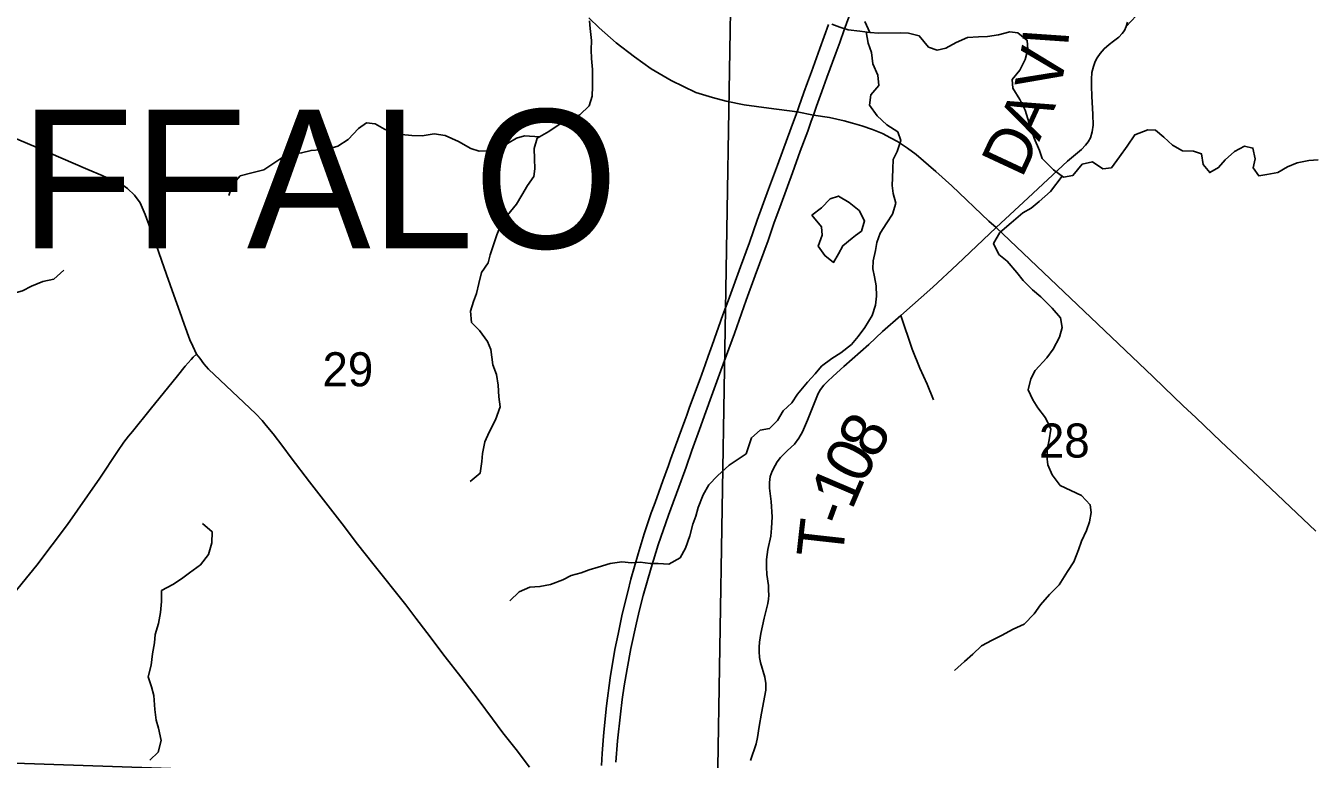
# Model space of a CAD drawing. Extents: x 0 to 34, y 0 to 22.
# Drawn here: x 6.508 to 8.087, y 16.577 to 17.478 of the extents above; entities that cross this region are included whole.
import ezdxf

# ---------------------------------------------------------------- set-up
doc = ezdxf.new("R2010")
doc.units = 0
for name, color, linetype in [('GM_X_Corporation', 7, 'Continuous'), ('GM_X_County_Road', 7, 'Continuous'), ('GM_X_County_Road_Text', 7, 'Continuous'), ('GM_X_Interstate_Route', 7, 'Continuous'), ('GM_X_Minor_Lake', 7, 'Continuous'), ('GM_X_Minor_River', 7, 'Continuous'), ('GM_X_Section_Text', 7, 'Continuous'), ('GM_X_State_Route', 7, 'Continuous'), ('GM_X_Township_Road', 7, 'Continuous'), ('GM_X_Township_Road_Text', 7, 'Continuous'), ('GM_X_Township_Text', 7, 'Continuous')]:
    doc.layers.add(name, color=color, linetype=linetype)

msp = doc.modelspace()

# ---------------------------------------------------------------- linework, layer by layer
at = {"layer": 'GM_X_Corporation'}
for points in [[(6.3854, 17.5878), (7.375, 17.5696), (7.3577, 16.5425), (6.3626, 16.5761)], [(7.375, 17.5696), (8.4063, 17.5538), (8.3875, 16.5502), (7.3577, 16.5425)]]:
    msp.add_lwpolyline(points, close=True, dxfattribs=at)
at = {"layer": 'GM_X_County_Road'}
for points in [[(7.8612, 17.4819), (7.8596, 17.4768)], [(7.8596, 17.4768), (7.8576, 17.4718), (7.8547, 17.468), (7.8507, 17.4635), (7.8441, 17.4588), (7.8386, 17.4544), (7.8325, 17.4493), (7.8276, 17.4437), (7.824, 17.4384), (7.8217, 17.4336), (7.8197, 17.4274), (7.8176, 17.4201), (7.8171, 17.4121), (7.8172, 17.4035), (7.8177, 17.3911), (7.8189, 17.3684), (7.819, 17.3553), (7.8178, 17.3472), (7.8159, 17.3401), (7.8132, 17.335), (7.8098, 17.3309), (7.8049, 17.3256), (7.7878, 17.3114), (7.7394, 17.2663), (7.6999, 17.2299)], [(7.1269, 16.5667), (7.1104, 16.5886), (7.094, 16.6091), (7.0812, 16.6263), (7.0639, 16.6502), (7.0426, 16.6779), (7.0231, 16.7026), (7.0009, 16.7322), (6.9871, 16.75), (6.9748, 16.7661), (6.9343, 16.8171), (6.9154, 16.841), (6.8968, 16.8657), (6.8565, 16.9175), (6.8342, 16.9467), (6.8238, 16.9606), (6.8118, 16.9763), (6.8035, 16.9865), (6.7983, 16.9928), (6.7908, 17.001), (6.7468, 17.0423), (6.7327, 17.0558), (6.7269, 17.0625), (6.7217, 17.0691), (6.7179, 17.0741), (6.7131, 17.084), (6.7098, 17.092), (6.7027, 17.1109), (6.6972, 17.1264), (6.6901, 17.1465), (6.6811, 17.1719), (6.6652, 17.2167), (6.6547, 17.2458), (6.6485, 17.2599), (6.6418, 17.2696), (6.633, 17.2777), (6.6272, 17.2817), (6.6189, 17.286), (6.602, 17.2938), (6.5842, 17.3012), (6.521, 17.3283), (6.4674, 17.3509)]]:
    msp.add_lwpolyline(points, dxfattribs=at)
at = {"layer": 'GM_X_Interstate_Route'}
for points in [[(7.4729, 17.3604), (7.4756, 17.3679), (7.4792, 17.3787), (7.486, 17.3967), (7.4922, 17.4142), (7.5031, 17.4439), (7.5079, 17.4571), (7.5134, 17.4725), (7.5247, 17.5037)], [(7.2154, 16.5688), (7.2161, 16.5835), (7.2176, 16.6048), (7.2185, 16.614), (7.2214, 16.6422), (7.2259, 16.6767), (7.2318, 16.7114), (7.2356, 16.7304), (7.2407, 16.7548), (7.2474, 16.7823), (7.2513, 16.7978), (7.2603, 16.829), (7.2678, 16.8537), (7.2764, 16.8792), (7.2799, 16.8886), (7.2831, 16.8978), (7.2906, 16.9187), (7.2974, 16.9373), (7.2999, 16.9449), (7.3105, 16.9737), (7.3176, 16.9927), (7.32, 16.9993), (7.3233, 17.009), (7.3363, 17.044), (7.3424, 17.0611), (7.3463, 17.0718), (7.3512, 17.0854), (7.3644, 17.1226), (7.3707, 17.1397), (7.3858, 17.1814), (7.3969, 17.2112), (7.4065, 17.2389), (7.4204, 17.277), (7.4313, 17.3063), (7.4438, 17.3401), (7.451, 17.3601), (7.4554, 17.3718), (7.4577, 17.3782), (7.4639, 17.3958), (7.4682, 17.4079), (7.4731, 17.4209), (7.4834, 17.4496), (7.4942, 17.4793)], [(7.2328, 16.573), (7.2348, 16.5992), (7.2384, 16.632), (7.2406, 16.6499), (7.243, 16.6667), (7.2468, 16.6875), (7.2513, 16.7125), (7.2583, 16.7442), (7.2619, 16.76), (7.2665, 16.7776), (7.2762, 16.8119), (7.285, 16.8399), (7.2975, 16.8763), (7.3129, 16.9187), (7.3192, 16.9354), (7.3263, 16.9557), (7.3374, 16.986), (7.3418, 16.9988), (7.352, 17.0272), (7.3619, 17.0542), (7.3786, 17.0996), (7.393, 17.1407), (7.4042, 17.1709), (7.4198, 17.214), (7.4271, 17.2345), (7.4359, 17.2587), (7.4497, 17.2968), (7.4594, 17.3237), (7.4686, 17.3482), (7.4729, 17.3604)]]:
    msp.add_lwpolyline(points, dxfattribs=at)
at = {"layer": 'GM_X_Minor_Lake'}
for points in [[(7.5274, 17.2198), (7.5347, 17.2253), (7.5384, 17.2378), (7.5316, 17.2507), (7.5194, 17.2605), (7.5062, 17.2684), (7.496, 17.265), (7.4854, 17.2539), (7.4737, 17.2448)], [(7.4737, 17.2448), (7.4855, 17.2308), (7.4862, 17.2202), (7.4814, 17.2069), (7.4894, 17.1952), (7.5004, 17.1869), (7.5064, 17.1975), (7.5117, 17.2074), (7.523, 17.2165), (7.5274, 17.2198)]]:
    msp.add_lwpolyline(points, dxfattribs=at)
at = {"layer": 'GM_X_Minor_River'}
for points in [[(7.2004, 17.4838), (7.2015, 17.4743), (7.2031, 17.4596), (7.2024, 17.4482), (7.2028, 17.4372), (7.2043, 17.4239), (7.2044, 17.4126), (7.204, 17.4031), (7.2037, 17.3913), (7.2003, 17.3792), (7.1886, 17.3682), (7.1776, 17.3628), (7.1659, 17.3578), (7.1504, 17.3479), (7.1364, 17.3395), (7.1327, 17.327), (7.1331, 17.3141), (7.1335, 17.302), (7.132, 17.2925), (7.1245, 17.2815), (7.1173, 17.2697), (7.1109, 17.2583), (7.0996, 17.245), (7.0917, 17.2329), (7.0868, 17.2207), (7.0834, 17.2109), (7.0785, 17.1961), (7.0759, 17.1862), (7.068, 17.1744), (7.0646, 17.1611), (7.0616, 17.1486), (7.0579, 17.1387), (7.0545, 17.127), (7.0557, 17.1133), (7.0656, 17.1031), (7.0751, 17.0899), (7.0793, 17.0801), (7.0816, 17.0611), (7.0862, 17.0494), (7.0885, 17.0361), (7.0893, 17.0217), (7.0908, 17.0096), (7.0852, 16.9937), (7.0773, 16.9785), (7.072, 16.9667), (7.069, 16.9523), (7.0683, 16.9424), (7.0661, 16.928), (7.054, 16.9177)], [(7.5385, 17.4827), (7.545, 17.4695)], [(7.5404, 17.47), (7.5427, 17.4562), (7.5469, 17.4448), (7.5485, 17.4308), (7.5546, 17.4168), (7.5558, 17.4043), (7.5459, 17.3929), (7.5445, 17.38), (7.554, 17.3671), (7.5657, 17.3558), (7.5794, 17.3471), (7.5828, 17.3365), (7.5783, 17.3233), (7.5734, 17.3134), (7.5731, 17.302), (7.5727, 17.291), (7.5724, 17.2812), (7.5736, 17.2717), (7.5766, 17.2596), (7.5725, 17.2463), (7.5657, 17.2356), (7.5574, 17.2227), (7.5533, 17.2113), (7.5518, 17.2015), (7.5488, 17.189), (7.5485, 17.1791), (7.5504, 17.1693), (7.5527, 17.1583), (7.5531, 17.1454), (7.552, 17.1344), (7.5475, 17.1215), (7.5385, 17.1071), (7.5305, 17.0957), (7.5222, 17.0861), (7.5094, 17.0759), (7.4981, 17.069), (7.4856, 17.0595), (7.4777, 17.05), (7.4682, 17.0397), (7.4558, 17.0249), (7.449, 17.0143), (7.4384, 17.0044), (7.4316, 16.9926), (7.4218, 16.9827), (7.4101, 16.9808), (7.3995, 16.9713), (7.3961, 16.9618), (7.3931, 16.9519), (7.3818, 16.9443), (7.372, 16.9378), (7.3576, 16.9249), (7.3471, 16.9138), (7.3403, 16.9013), (7.3339, 16.8857), (7.3313, 16.8751), (7.3275, 16.8652), (7.3238, 16.8512), (7.3185, 16.836), (7.3117, 16.8239), (7.2981, 16.8162), (7.2849, 16.817), (7.275, 16.8169), (7.2629, 16.8188), (7.2523, 16.818), (7.2402, 16.8191), (7.2258, 16.8171), (7.2111, 16.8125), (7.2001, 16.8091), (7.1902, 16.8056), (7.1781, 16.8022), (7.1676, 16.7968), (7.1528, 16.7911), (7.1396, 16.7888), (7.1274, 16.788), (7.1142, 16.7822), (7.1025, 16.7712)], [(7.498, 17.4795), (7.5078, 17.4758), (7.5184, 17.4728), (7.5325, 17.4709), (7.545, 17.4695)], [(7.545, 17.4695), (7.5559, 17.4687), (7.5821, 17.4688), (7.5923, 17.4685), (7.6056, 17.4651), (7.617, 17.4515), (7.6276, 17.4478), (7.6382, 17.4501), (7.651, 17.4569), (7.665, 17.463), (7.6783, 17.4642), (7.6892, 17.4643), (7.7029, 17.4666), (7.7169, 17.47), (7.7267, 17.4689), (7.7381, 17.4595), (7.7389, 17.4485), (7.7355, 17.436), (7.7291, 17.4231)], [(7.7291, 17.4231), (7.7197, 17.4117), (7.7205, 17.4011), (7.7292, 17.3871), (7.7357, 17.3738), (7.7388, 17.3632), (7.7426, 17.3515), (7.7468, 17.3394), (7.7533, 17.3242), (7.7567, 17.3144), (7.7704, 17.3008), (7.7829, 17.2917), (7.7942, 17.2937), (7.8056, 17.3074), (7.8184, 17.3104), (7.8309, 17.3018), (7.8415, 17.3029), (7.8517, 17.3166), (7.8608, 17.3299), (7.8702, 17.3436), (7.8861, 17.3497), (7.8959, 17.3494), (7.9058, 17.3407), (7.9164, 17.3309), (7.9289, 17.3241), (7.9422, 17.3237), (7.9521, 17.3204), (7.9544, 17.3071), (7.9623, 17.2973), (7.9733, 17.3034), (7.9812, 17.3129), (7.9926, 17.3232), (8.005, 17.3296), (8.0153, 17.3274), (8.0183, 17.3141), (8.0157, 17.3031), (8.0226, 17.2933), (8.0324, 17.2949), (8.046, 17.2972), (8.0577, 17.3044), (8.0698, 17.3094), (8.0842, 17.3121), (8.0956, 17.3129)], [(7.1394, 17.3413), (7.1205, 17.3425), (7.1107, 17.3395), (7.0997, 17.333), (7.0884, 17.328), (7.0755, 17.3238), (7.0649, 17.3234), (7.0547, 17.3267), (7.0395, 17.3354), (7.0232, 17.3429), (7.0096, 17.3448), (6.9948, 17.3425), (6.9823, 17.3428), (6.9694, 17.3439), (6.9596, 17.3461), (6.9486, 17.3506), (6.9372, 17.357), (6.9266, 17.3585), (6.9168, 17.3513), (6.9039, 17.338), (6.8915, 17.3296), (6.8816, 17.3269), (6.8695, 17.3253), (6.8586, 17.3245), (6.8468, 17.3215), (6.8336, 17.3203), (6.8226, 17.3153), (6.8128, 17.3088), (6.8007, 17.3008), (6.7859, 17.297), (6.7716, 17.2932), (6.7617, 17.2817), (6.7576, 17.2692)], [(7.7812, 17.293), (7.7667, 17.2739), (7.7527, 17.2617), (7.7429, 17.2537), (7.7327, 17.248), (7.7183, 17.2354), (7.7047, 17.2236), (7.6968, 17.2103), (7.7033, 17.1967), (7.7135, 17.1884), (7.7253, 17.1744), (7.7333, 17.1646), (7.7447, 17.1532), (7.7549, 17.1446), (7.7686, 17.1306), (7.7789, 17.1189), (7.7812, 17.1068), (7.7778, 17.095), (7.7699, 17.0802), (7.7623, 17.0695), (7.748, 17.0543), (7.7427, 17.0441), (7.7394, 17.0304), (7.7451, 17.0183), (7.7512, 17.0081), (7.7607, 16.996), (7.7671, 16.982), (7.7653, 16.9691), (7.763, 16.9592), (7.7623, 16.949), (7.7635, 16.9384), (7.7688, 16.9259), (7.7787, 16.913), (7.7916, 16.9066), (7.8049, 16.9006), (7.8155, 16.8893), (7.8167, 16.8798), (7.8148, 16.8681), (7.8111, 16.8574), (7.805, 16.8445), (7.8013, 16.8339), (7.7956, 16.8191), (7.7877, 16.8073), (7.7772, 16.791), (7.7655, 16.7788), (7.7545, 16.7663), (7.7466, 16.7552), (7.7345, 16.7427), (7.7209, 16.7366), (7.7065, 16.7286), (7.6952, 16.7228), (7.682, 16.716), (7.6714, 16.7057), (7.6612, 16.6966), (7.6487, 16.6855)], [(6.3117, 17.119), (6.3215, 17.1194), (6.3317, 17.1237), (6.3434, 17.1286), (6.3537, 17.1309), (6.3643, 17.1314), (6.3752, 17.1318), (6.4025, 17.1394), (6.4169, 17.1376), (6.4282, 17.1373), (6.4381, 17.1358), (6.4525, 17.1381), (6.4657, 17.1431), (6.4778, 17.1465), (6.4892, 17.1481), (6.5039, 17.1519), (6.5153, 17.1577), (6.5289, 17.1634), (6.5425, 17.1665), (6.555, 17.1775)], [(6.6744, 16.5995), (6.671, 16.6146), (6.6683, 16.6245), (6.6667, 16.6378), (6.6655, 16.6548), (6.6625, 16.6654), (6.6583, 16.6779), (6.662, 16.6923), (6.6639, 16.706), (6.6661, 16.7196), (6.6672, 16.7299), (6.6713, 16.7435), (6.6736, 16.7568), (6.6747, 16.7705), (6.675, 16.7837), (6.6886, 16.7914), (6.6992, 16.7982), (6.709, 16.8055), (6.7226, 16.8154), (6.7324, 16.8283), (6.7365, 16.8423), (6.7369, 16.856), (6.7251, 16.8662)], [(6.6605, 16.5756), (6.6707, 16.5855), (6.6744, 16.5995)]]:
    msp.add_lwpolyline(points, dxfattribs=at)
at = {"layer": 'GM_X_State_Route'}
msp.add_lwpolyline([(7.1997, 17.4872), (7.2122, 17.4752), (7.2333, 17.4566), (7.2556, 17.4396), (7.2764, 17.4245), (7.301, 17.4105), (7.3312, 17.3956), (7.3516, 17.3893), (7.3684, 17.3849), (7.3905, 17.3805), (7.4209, 17.3763), (7.4554, 17.3718), (7.4756, 17.3679), (7.4951, 17.3649), (7.5132, 17.361), (7.5237, 17.3581), (7.5352, 17.3548), (7.5483, 17.3502), (7.5605, 17.3451), (7.5703, 17.3401), (7.5787, 17.3353), (7.5913, 17.3272), (7.6016, 17.3193), (7.6259, 17.2986), (7.6457, 17.2809), (7.6911, 17.2377), (7.6999, 17.2299), (7.8164, 17.1191), (7.8924, 17.0467), (7.9062, 17.0334), (7.9293, 17.011), (7.9455, 16.9958), (7.9761, 16.9669), (8.0217, 16.9241), (8.0534, 16.894), (8.0928, 16.8569)], dxfattribs=at)
at = {"layer": 'GM_X_Township_Road'}
for points in [[(7.8781, 17.4963), (7.8596, 17.4768)], [(7.8596, 17.4768), (7.8576, 17.4718), (7.8547, 17.468), (7.8507, 17.4635), (7.8441, 17.4588), (7.8386, 17.4544), (7.8325, 17.4493), (7.8276, 17.4437), (7.824, 17.4384), (7.8217, 17.4336), (7.8197, 17.4274), (7.8176, 17.4201), (7.8171, 17.4121), (7.8172, 17.4035), (7.8177, 17.3911), (7.8189, 17.3684), (7.819, 17.3553), (7.8178, 17.3472), (7.8159, 17.3401), (7.8132, 17.335), (7.8098, 17.3309), (7.8049, 17.3256), (7.7878, 17.3114), (7.7394, 17.2663), (7.6999, 17.2299)], [(7.6999, 17.2299), (7.6523, 17.1844), (7.6222, 17.1566), (7.5828, 17.1216), (7.5606, 17.102), (7.5438, 17.0861), (7.5131, 17.0589), (7.4999, 17.0473), (7.4927, 17.0407), (7.4882, 17.036), (7.4842, 17.0309), (7.4813, 17.0257), (7.4773, 17.0157), (7.4731, 17.0055), (7.4684, 16.9933), (7.4621, 16.9789), (7.4577, 16.9709), (7.4524, 16.9636), (7.4437, 16.9557), (7.435, 16.9474), (7.4311, 16.942), (7.4286, 16.9376), (7.425, 16.9304), (7.4226, 16.9241), (7.4214, 16.9167), (7.4217, 16.9096), (7.4238, 16.8931), (7.4247, 16.8743), (7.4241, 16.8603), (7.4231, 16.8508), (7.4196, 16.8344), (7.4181, 16.8221), (7.4179, 16.8125), (7.4184, 16.8034), (7.4202, 16.7899), (7.4204, 16.7845), (7.4206, 16.7782), (7.4203, 16.7733), (7.4194, 16.768), (7.4151, 16.7498), (7.411, 16.7311), (7.4092, 16.7203), (7.4088, 16.7142), (7.4088, 16.7089), (7.4093, 16.7016), (7.4106, 16.6953), (7.4157, 16.6776), (7.4172, 16.6698), (7.4173, 16.6615), (7.4118, 16.6334), (7.4088, 16.6167), (7.4067, 16.6033), (7.4051, 16.5955), (7.3981, 16.5751)], [(7.6231, 17.0179), (7.6153, 17.0374), (7.6064, 17.0572), (7.597, 17.0804), (7.5828, 17.1216)], [(6.4893, 16.7752), (6.5216, 16.8149), (6.5594, 16.8648), (6.5716, 16.8824), (6.5991, 16.922), (6.6209, 16.9546), (6.6287, 16.966), (6.6342, 16.9733), (6.639, 16.9792), (6.661, 17.0063), (6.6945, 17.0476), (6.7038, 17.0595), (6.7111, 17.0677), (6.7139, 17.0707), (6.7179, 17.0741)]]:
    msp.add_lwpolyline(points, dxfattribs=at)

# ---------------------------------------------------------------- texts
at = {"layer": 'GM_X_County_Road_Text'}
for s, rotation, p in [('I', 86.0486, (7.7885, 17.4509)), ('V', 79.2664, (7.7782, 17.3945)), ('A', 65.3246, (7.7528, 17.3347)), ('D', 64.9844, (7.7315, 17.2891))]:
    msp.add_text(s, height=0.0568, rotation=rotation, dxfattribs=at).set_placement(p)
at = {"layer": 'GM_X_Section_Text'}
for s, p in [('29', (6.8726, 17.0347)), ('28', (7.7526, 16.9472))]:
    msp.add_text(s, height=0.04186, rotation=0, dxfattribs=at).set_placement(p)
at = {"layer": 'GM_X_Township_Road_Text'}
for s, rotation, p in [('8', 60.3055, (7.5518, 16.9432)), ('0', 62.4993, (7.536, 16.9126)), ('1', 66.9606, (7.5228, 16.8815)), ('-', 69.8468, (7.515, 16.8603)), ('T', 83.5926, (7.5111, 16.8216))]:
    msp.add_text(s, height=0.0568, rotation=rotation, dxfattribs=at).set_placement(p)
at = {"layer": 'GM_X_Township_Text'}
msp.add_text('BUFFALO', height=0.17045, rotation=0, dxfattribs=at).set_placement((6.1846, 17.2042))

doc.saveas('drawing.dxf')
